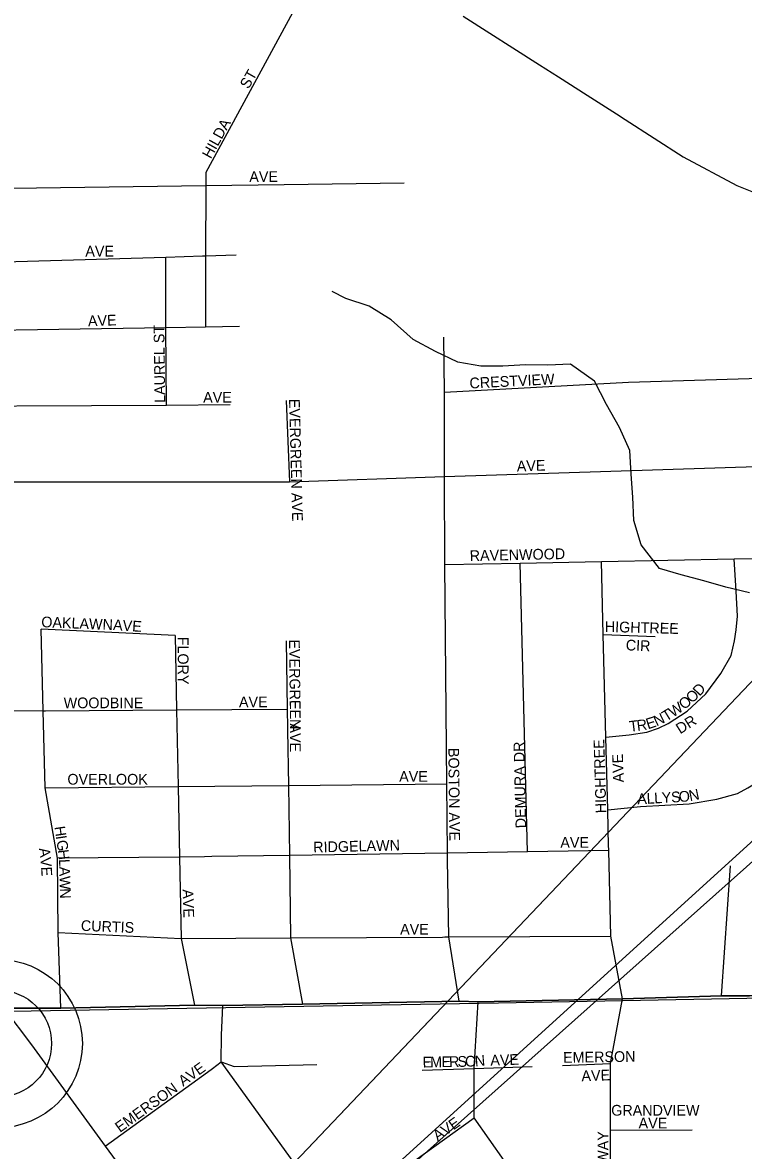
# Model space of a CAD drawing. Extents: x -37878.7 to -37844.7, y -19791.4 to -19769.4.
# Drawn here: x -37873.473 to -37872.836, y -19774.18 to -19773.183 of the extents above; entities that cross this region are included whole.
import ezdxf

# ---------------------------------------------------------------- set-up
doc = ezdxf.new("R2010")
doc.units = 0
for name, color, linetype in [('Default', 7, 'Continuous'), ('GM_X_City_Street', 7, 'Continuous'), ('GM_X_County_Road', 7, 'Continuous'), ('GM_X_Minor_River', 7, 'Continuous'), ('GM_X_Section', 7, 'Continuous'), ('GM_X_State_Route', 7, 'Continuous'), ('GM_X_Township', 7, 'Continuous'), ('GM_X_Township_Subdivision', 7, 'Continuous'), ('GM_X_Township_Subdivision_Text', 7, 'Continuous'), ('GM_X_Unincorporated', 7, 'Continuous'), ('GM_X_US_Route', 7, 'Continuous'), ('TX_P_1', 7, 'Continuous')]:
    doc.layers.add(name, color=color, linetype=linetype)

msp = doc.modelspace()

# ---------------------------------------------------------------- linework, layer by layer
at = {"layer": 'Default'}
msp.add_lwpolyline([(-37873.34641, -19773.45227), (-37873.34641, -19773.39006)], dxfattribs=at)
at = {"layer": 'GM_X_City_Street'}
for points in [[(-37872.85505, -19774.04299), (-37872.84709, -19773.92802)], [(-37872.85505, -19774.04299), (-37872.83024, -19774.0429)]]:
    msp.add_lwpolyline(points, dxfattribs=at)
at = {"layer": 'GM_X_County_Road'}
for points in [[(-37873.48951, -19774.05375), (-37873.48951, -19774.05375), (-37873.43906, -19774.05375), (-37873.321, -19774.05101), (-37873.29591, -19774.0514), (-37873.22557, -19774.05028), (-37873.08696, -19774.04763), (-37873.07008, -19774.04829), (-37872.94239, -19774.04564), (-37872.88479, -19774.04389)], [(-37872.88479, -19774.04389), (-37872.85505, -19774.04299)]]:
    msp.add_lwpolyline(points, dxfattribs=at)
at = {"layer": 'GM_X_Minor_River'}
msp.add_lwpolyline([(-37872.83014, -19773.68671), (-37872.85108, -19773.68184), (-37872.87052, -19773.67618), (-37872.89071, -19773.67092), (-37872.90977, -19773.66525), (-37872.92612, -19773.64434), (-37872.93263, -19773.62284), (-37872.93343, -19773.60236), (-37872.93499, -19773.5819), (-37872.93619, -19773.56104), (-37872.94532, -19773.54074), (-37872.95673, -19773.52048), (-37872.96739, -19773.49983), (-37872.98854, -19773.48472), (-37873.0086, -19773.48553), (-37873.02831, -19773.48519), (-37873.04836, -19773.48638), (-37873.06768, -19773.48641), (-37873.08821, -19773.48305), (-37873.10773, -19773.4736), (-37873.12765, -19773.46301), (-37873.14695, -19773.44558), (-37873.16653, -19773.43348), (-37873.18712, -19773.42671), (-37873.19938, -19773.42051)], dxfattribs=at)
at = {"layer": 'GM_X_Section'}
msp.add_lwpolyline([(-37872.18692, -19774.08978), (-37872.17025, -19774.67952), (-37872.58024, -19774.69042), (-37872.96634, -19774.70069), (-37873.29687, -19774.70587), (-37873.69019, -19774.71163), (-37873.75987, -19774.71265), (-37873.7756, -19774.06152), (-37873.05223, -19774.04922), (-37872.2676, -19774.03426)], dxfattribs=at)
at = {"layer": 'GM_X_State_Route'}
msp.add_lwpolyline([(-37873.95248, -19773.43587), (-37873.95162, -19773.43705), (-37873.92896, -19773.46717), (-37873.88141, -19773.53302), (-37873.82083, -19773.61513), (-37873.73521, -19773.73227), (-37873.66482, -19773.82552), (-37873.65587, -19773.8369), (-37873.63173, -19773.86938), (-37873.58708, -19773.92637), (-37873.54786, -19773.97819), (-37873.48951, -19774.05375), (-37873.46508, -19774.08632), (-37873.39994, -19774.17562), (-37873.33244, -19774.26754), (-37873.29909, -19774.31219), (-37873.26468, -19774.35921), (-37873.23106, -19774.40478), (-37873.19745, -19774.45126), (-37873.12863, -19774.54293), (-37873.06297, -19774.63485), (-37873.04491, -19774.65944)], dxfattribs=at)
at = {"layer": 'GM_X_Township'}
for points in [[(-37872.2676, -19774.0341), (-37872.38016, -19774.03604), (-37872.76408, -19774.04266), (-37872.85506, -19774.043), (-37872.94239, -19774.04564), (-37873.07009, -19774.04829), (-37873.08696, -19774.04763), (-37873.22557, -19774.05027), (-37873.2959, -19774.0514), (-37873.32101, -19774.05101), (-37873.43906, -19774.05375), (-37873.48951, -19774.05375), (-37873.76133, -19774.06615), (-37873.82094, -19774.06728), (-37873.90676, -19774.06892), (-37874.01664, -19774.06271), (-37874.41791, -19774.07867), (-37875.13726, -19774.08233), (-37875.16478, -19772.49865)], [(-37875.12559, -19774.70629), (-37875.12978, -19774.45993), (-37875.13234, -19774.33027), (-37875.13726, -19774.08233), (-37874.41791, -19774.07867), (-37874.01664, -19774.06271), (-37873.90676, -19774.06892), (-37873.82094, -19774.06728), (-37873.76133, -19774.06615), (-37873.48951, -19774.05375), (-37873.43906, -19774.05375), (-37873.32101, -19774.05101), (-37873.2959, -19774.0514), (-37873.22557, -19774.05027), (-37873.08696, -19774.04763), (-37873.07009, -19774.04829), (-37872.94239, -19774.04564), (-37872.85506, -19774.043), (-37872.76408, -19774.04266), (-37872.38016, -19774.03604), (-37872.2676, -19774.0341)]]:
    msp.add_lwpolyline(points, dxfattribs=at)
at = {"layer": 'GM_X_Township_Subdivision'}
for points in [[(-37873.1969, -19773.10509), (-37873.31101, -19773.3154), (-37873.31103, -19773.32681), (-37873.31115, -19773.38901), (-37873.31127, -19773.45171)], [(-37873.58959, -19773.33068), (-37873.31103, -19773.32681), (-37873.24179, -19773.32585)], [(-37873.24179, -19773.32585), (-37873.24179, -19773.32585), (-37873.13551, -19773.32437)], [(-37873.97578, -19773.40402), (-37873.7765, -19773.40279), (-37873.61179, -19773.39791), (-37873.34641, -19773.39006), (-37873.31379, -19773.38909)], [(-37873.31379, -19773.38909), (-37873.31365, -19773.38909), (-37873.31115, -19773.38901), (-37873.28415, -19773.38822)], [(-37873.92896, -19773.46717), (-37873.77763, -19773.45923), (-37873.61144, -19773.45655), (-37873.34641, -19773.45227), (-37873.31127, -19773.45171), (-37873.28126, -19773.45122)], [(-37873.34564, -19773.52088), (-37873.34641, -19773.45227)], [(-37873.09723, -19773.91894), (-37873.09725, -19773.91758), (-37873.09726, -19773.91668), (-37873.09785, -19773.8557), (-37873.09972, -19773.66174), (-37873.09979, -19773.58392), (-37873.09986, -19773.52014), (-37873.09997, -19773.50951), (-37873.10046, -19773.46093)], [(-37873.09997, -19773.50951), (-37872.93733, -19773.50051), (-37872.77219, -19773.49563), (-37872.75928, -19773.4937), (-37872.75012, -19773.4937), (-37872.73763, -19773.49553), (-37872.72831, -19773.49901), (-37872.70769, -19773.51396), (-37872.7068, -19773.51452), (-37872.70457, -19773.51487), (-37872.68886, -19773.51729), (-37872.67489, -19773.51509), (-37872.65437, -19773.50725)], [(-37873.61104, -19773.52206), (-37873.34564, -19773.52088), (-37873.28936, -19773.52033)], [(-37873.24001, -19773.51677), (-37873.23709, -19773.58883)], [(-37873.60284, -19773.58861), (-37873.23709, -19773.58883), (-37873.09979, -19773.58392), (-37872.66782, -19773.57005)], [(-37873.09972, -19773.66174), (-37873.03288, -19773.66045), (-37872.96112, -19773.65906), (-37872.84377, -19773.6568), (-37872.81262, -19773.65632), (-37872.79973, -19773.65787), (-37872.77728, -19773.66267), (-37872.7609, -19773.66831), (-37872.74425, -19773.65764), (-37872.73528, -19773.65506), (-37872.72468, -19773.65374), (-37872.71123, -19773.65374), (-37872.69308, -19773.65916)], [(-37873.02663, -19773.91561), (-37873.03288, -19773.66045)], [(-37872.95481, -19773.91096), (-37872.95562, -19773.87847), (-37872.95723, -19773.8143), (-37872.95951, -19773.72359), (-37872.96112, -19773.65906)], [(-37872.95723, -19773.8143), (-37872.93661, -19773.81233), (-37872.92106, -19773.81001), (-37872.91065, -19773.80636), (-37872.90209, -19773.80236), (-37872.88542, -19773.7913), (-37872.86877, -19773.77607), (-37872.85554, -19773.75818), (-37872.84649, -19773.74221), (-37872.84348, -19773.72914), (-37872.84215, -19773.71942), (-37872.84092, -19773.70728), (-37872.84213, -19773.68543), (-37872.84377, -19773.6568)], [(-37872.95562, -19773.87847), (-37872.9265, -19773.87569), (-37872.8836, -19773.87329), (-37872.85904, -19773.8691), (-37872.84072, -19773.86405), (-37872.83165, -19773.85896), (-37872.82149, -19773.85279), (-37872.81041, -19773.8446), (-37872.80738, -19773.84086), (-37872.80382, -19773.83646), (-37872.79719, -19773.82323), (-37872.79154, -19773.81228), (-37872.77885, -19773.75113), (-37872.7609, -19773.66831)], [(-37873.3382, -19773.72443), (-37873.45661, -19773.71893)], [(-37873.43906, -19774.05375), (-37873.44157, -19773.98704), (-37873.4421, -19773.92112), (-37873.45291, -19773.85903), (-37873.4547, -19773.79115), (-37873.45661, -19773.71893)], [(-37873.3382, -19773.72443), (-37873.33687, -19773.79025), (-37873.3355, -19773.85793), (-37873.33424, -19773.92028), (-37873.33278, -19773.99232), (-37873.321, -19774.05101)], [(-37873.2399, -19773.72928), (-37873.239, -19773.78953), (-37873.23874, -19773.80609), (-37873.23871, -19773.80822)], [(-37872.95951, -19773.72359), (-37872.91377, -19773.72534)], [(-37873.62542, -19773.77824), (-37873.60546, -19773.78795), (-37873.5968, -19773.79032), (-37873.58708, -19773.79084), (-37873.4547, -19773.79115), (-37873.45282, -19773.7911), (-37873.33687, -19773.79025), (-37873.239, -19773.78953)], [(-37873.23871, -19773.80822), (-37873.23798, -19773.85702), (-37873.23705, -19773.91881), (-37873.23595, -19773.99172), (-37873.22557, -19774.05028)], [(-37873.45291, -19773.85903), (-37873.3355, -19773.85793), (-37873.23798, -19773.85702), (-37873.09785, -19773.8557)], [(-37872.94239, -19774.04564), (-37872.95283, -19773.99002), (-37872.95471, -19773.91452), (-37872.95476, -19773.91298), (-37872.95481, -19773.91096)], [(-37873.30562, -19773.91984), (-37873.31223, -19773.91994), (-37873.33424, -19773.92028), (-37873.4421, -19773.92112)], [(-37872.95471, -19773.91452), (-37873.02663, -19773.91561), (-37873.09726, -19773.91668), (-37873.23705, -19773.91881), (-37873.30562, -19773.91984)], [(-37873.08696, -19774.04763), (-37873.09616, -19773.99088), (-37873.09718, -19773.92259), (-37873.09723, -19773.91894)], [(-37873.44157, -19773.98704), (-37873.33278, -19773.99232), (-37873.23595, -19773.99172), (-37873.1018, -19773.99092), (-37873.09949, -19773.9909)], [(-37873.09949, -19773.9909), (-37873.09616, -19773.99088), (-37872.95283, -19773.99002)], [(-37873.02571, -19774.47517), (-37873.02863, -19774.47124), (-37873.09606, -19774.37746), (-37873.12968, -19774.33123), (-37873.16435, -19774.28435), (-37873.19745, -19774.23971), (-37873.23001, -19774.19453), (-37873.29736, -19774.10122), (-37873.29703, -19774.07773), (-37873.29591, -19774.0514)], [(-37872.96881, -19774.28686), (-37873.00724, -19774.24507), (-37873.07359, -19774.15057), (-37873.07378, -19774.107), (-37873.07008, -19774.04829)], [(-37872.95299, -19774.26503), (-37872.95299, -19774.22064), (-37872.953, -19774.16159), (-37872.95301, -19774.10276), (-37872.94239, -19774.04564)], [(-37873.30513, -19774.1071), (-37873.29736, -19774.10122), (-37873.28578, -19774.10519), (-37873.21267, -19774.10353)], [(-37873.39994, -19774.17562), (-37873.3096, -19774.11048), (-37873.30513, -19774.1071)], [(-37873.11971, -19774.10858), (-37873.07378, -19774.107), (-37873.02249, -19774.10525)], [(-37872.99553, -19774.10441), (-37872.95301, -19774.10276)], [(-37873.29909, -19774.31219), (-37873.19745, -19774.23971), (-37873.07359, -19774.15057)], [(-37872.953, -19774.16159), (-37872.881, -19774.16138)]]:
    msp.add_lwpolyline(points, dxfattribs=at)
at = {"layer": 'GM_X_Unincorporated'}
for radius in [0.0744, 0.04716]:
    msp.add_circle((-37873.49453, -19774.08503), radius, dxfattribs=at)
at = {"layer": 'GM_X_US_Route'}
for points in [[(-37873.0834, -19773.17729), (-37873.01592, -19773.22022)], [(-37873.01592, -19773.22022), (-37872.99905, -19773.23095)], [(-37872.99905, -19773.23095), (-37872.97374, -19773.24705)], [(-37872.97374, -19773.24705), (-37872.94772, -19773.26361), (-37872.94003, -19773.26856)], [(-37872.94003, -19773.26856), (-37872.88901, -19773.30144), (-37872.84139, -19773.32688), (-37872.79877, -19773.34398), (-37872.7554, -19773.35776), (-37872.72529, -19773.36184), (-37872.63243, -19773.37204)]]:
    msp.add_lwpolyline(points, dxfattribs=at)
at = {"layer": 'TX_P_1'}
for p, q in [((-37871.71882, -19772.5985), (-37873.82258, -19774.8103)), ((-37873.82258, -19774.8103), (-37871.71882, -19772.89801))]:
    msp.add_line(p, q, dxfattribs=at)
msp.add_lwpolyline([(-37871.71882, -19772.5985), (-37873.82258, -19774.8103), (-37871.71882, -19772.93626)], close=True, dxfattribs=at)

# ---------------------------------------------------------------- texts
at = {"layer": 'GM_X_Township_Subdivision_Text'}
for s, height, rotation, p in [('ST', 0.00947, 60.24503, (-37873.27321, -19773.24215)), ('HILDA', 0.00947, 61.07374, (-37873.30655, -19773.30384)), ('AVE', 0.00947, 0.00001, (-37873.2725, -19773.32376)), ('AVE', 0.00947, 0.00001, (-37873.41749, -19773.38959)), ('AVE', 0.00947, 1.97389, (-37873.41505, -19773.45126)), ('LAUREL ST', 0.00947, 90.77379, (-37873.34678, -19773.51889)), ('CRESTVIEW', 0.00947, 2.89842, (-37873.07759, -19773.50626)), ('AVE', 0.00947, 0.00001, (-37873.31333, -19773.51875)), ('EVERGREEN AVE', 0.0094696, 271.49352, (-37873.23738, -19773.51549)), ('AVE', 0.00947, 1.97389, (-37873.03589, -19773.57959)), ('RAVENWOOD', 0.00947, 1.25956, (-37873.07754, -19773.65876)), ('OAKLAWN', 0.00947, 357.61393, (-37873.45659, -19773.71709)), ('AVE', 0.00947, 356.0574, (-37873.3932, -19773.71959)), ('HIGHTREE', 0.00947, 358.33905, (-37872.95828, -19773.72125)), ('FLORY', 0.00947, 270, (-37873.33571, -19773.72554)), ('EVERGREEN', 0.00947, 270.6899, (-37873.23738, -19773.72801)), ('CIR', 0.00947, 357.50694, (-37872.93979, -19773.73753)), ('D', 0.00947, 47.03943, (-37872.87446, -19773.77863)), ('WOODBINE', 0.00947, 0.00001, (-37873.43666, -19773.78875)), ('AVE', 0.00947, 0.00001, (-37873.28166, -19773.78792)), ('O', 0.00947, 39.6236, (-37872.88802, -19773.79046)), ('O', 0.00947, 42.2365, (-37872.88125, -19773.78484)), ('T', 0.00947, 31.62615, (-37872.90391, -19773.80077)), ('W', 0.00947, 33.44929, (-37872.89796, -19773.7971)), ('AVE', 0.00947, 270, (-37873.23655, -19773.8022)), ('T', 0.00947, 7.04028, (-37872.936, -19773.80959)), ('R', 0.00947, 7.23493, (-37872.92935, -19773.80877)), ('E', 0.00947, 17.75053, (-37872.92006, -19773.80742)), ('N', 0.00947, 25.37403, (-37872.91243, -19773.80488)), ('DR', 0.00947, 32.00784, (-37872.89157, -19773.81186)), ('DEMURA DR', 0.00947, 91.3796, (-37873.02761, -19773.89474)), ('HIGHTREE', 0.00947, 91.65937, (-37872.95678, -19773.88142)), ('BOSTON AVE', 0.00947, 270.6532, (-37873.09655, -19773.82385)), ('AVE', 0.00947, 91.97378, (-37872.94133, -19773.8542)), ('OVERLOOK', 0.00947, 0.00001, (-37873.43333, -19773.85625)), ('AVE', 0.00947, 0.00001, (-37873.14, -19773.85375)), ('O', 0.00947, 4.40008, (-37872.89242, -19773.87171)), ('N', 0.00947, 11.6573, (-37872.88282, -19773.87089)), ('A', 0.00947, 3.18226, (-37872.92926, -19773.87376)), ('L', 0.00947, 3.17074, (-37872.92094, -19773.87329)), ('L', 0.00947, 3.18576, (-37872.91428, -19773.87292)), ('Y', 0.00947, 3.18226, (-37872.90762, -19773.87255)), ('S', 0.00947, 3.17074, (-37872.8993, -19773.87209)), ('H', 0.00947, 278.53348, (-37873.4449, -19773.8936)), ('I', 0.00947, 278.58927, (-37873.44366, -19773.90185)), ('G', 0.00947, 278.53348, (-37873.44304, -19773.90596)), ('RIDGELAWN', 0.00947, 1.36448, (-37873.21587, -19773.91625)), ('AVE', 0.00947, 0.00001, (-37872.9975, -19773.91209)), ('A', 0.00947, 277.87199, (-37873.45851, -19773.9127)), ('V', 0.00947, 275.09945, (-37873.45738, -19773.92084)), ('H', 0.00947, 276.94608, (-37873.44181, -19773.91414)), ('E', 0.00947, 273.2253, (-37873.45664, -19773.92905)), ('L', 0.00947, 272.43259, (-37873.44082, -19773.92221)), ('A', 0.00947, 271.39905, (-37873.44054, -19773.92883)), ('W', 0.00947, 271.37875, (-37873.44034, -19773.93716)), ('N', 0.00947, 271.35535, (-37873.44007, -19773.94798)), ('AVE', 0.00947, 271.97378, (-37873.33155, -19773.94881)), ('CURTIS', 0.00947, 357.66397, (-37873.42159, -19773.98542)), ('AVE', 0.00947, 0.00001, (-37873.13916, -19773.98875)), ('E', 0.00947, 1.07912, (-37873.11919, -19774.10625)), ('M', 0.00947, 1.08383, (-37873.11252, -19774.10612)), ('E', 0.00947, 1.07912, (-37873.10253, -19774.10594)), ('R', 0.00947, 1.07449, (-37873.09586, -19774.10581)), ('S', 0.00947, 1.07912, (-37873.08836, -19774.10567)), ('O', 0.00947, 1.90293, (-37873.08155, -19774.10554)), ('N', 0.00947, 4.3715, (-37873.07277, -19774.10524)), ('AVE', 0.00947, 1.97766, (-37873.05923, -19774.10459)), ('EMERSON', 0.00947, 0.86755, (-37872.99502, -19774.10208)), ('AVE', 0.00947, 35.30919, (-37873.33102, -19774.12325)), ('AVE', 0.00947, 1.97389, (-37872.97866, -19774.11837)), ('EMERSON', 0.00947, 35.83883, (-37873.38687, -19774.16409)), ('GRANDVIEW', 0.00947, 0.00001, (-37872.9525, -19774.14875)), ('AVE', 0.00947, 34.82268, (-37873.10601, -19774.17157)), ('AVE', 0.00947, 0.00001, (-37872.92833, -19774.16004)), ('BROADWAY', 0.00947, 90, (-37872.95511, -19774.23637))]:
    msp.add_text(s, height=height, rotation=rotation, dxfattribs=at).set_placement(p)

doc.saveas('drawing.dxf')
